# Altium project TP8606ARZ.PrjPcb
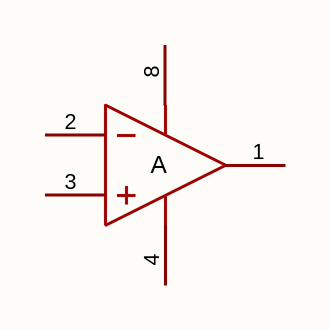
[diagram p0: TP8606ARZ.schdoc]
1 sheet, 1 parts. Net scope: global (net labels, ports and power ports of the same name join across sheets).

## Sheet TP8606ARZ.schdoc
size 127 x 101 mm

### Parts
U?  tp8606arz  [SOIC-8_L4.9-W3.9-P1.27-LS6.0-BL]  (value not drawn)  (part A of 2)

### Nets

Not connected (* = marked no-connect by the designer): U? 1(OUTA) 2(-INA) 3(+INA) 4(-VS) 8(+VS)

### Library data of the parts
U? = tp8606arz: 放大器数:2;轨到轨:轨到轨输入,轨到轨输出;增益带宽积(GBW):10MHz;输入失调电压(Vos):5mV;压摆率(SR):4.5V/us;输入偏置电流(Ib):100pA;; Manufacturer: TECH PUBLIC(台舟); AddInBom: yes; ModelId: e81d2f7d937b4a6ab1dca543ff5d56a4; ModelName: SOIC-8_L4.9-W3.9-H1.7-LS6.0-P1.27; ModelTransform: 192.913,236.22,0,0,0,0,0,0,0; Number of Channels: 2; Maximum Power Supply Range (Vdd-Vss): 7V; Gain Bandwidth Product: 10MHz; Vos - Input Offset Voltage: 5mV; Input Offset Voltage Drift(Vos TC): 1.5uV/℃; Ib - Input Bias Current: 100pA; Input Offset Current(Ios): 1pA; Input Voltage Noise Density: 15nV/√Hz@30kHz; Common Mode Rejection Ratio(CMRR): 90dB; Quiescent Current: 800uA; Output Current: 50mA; Single supply: 2.2V~5.5V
